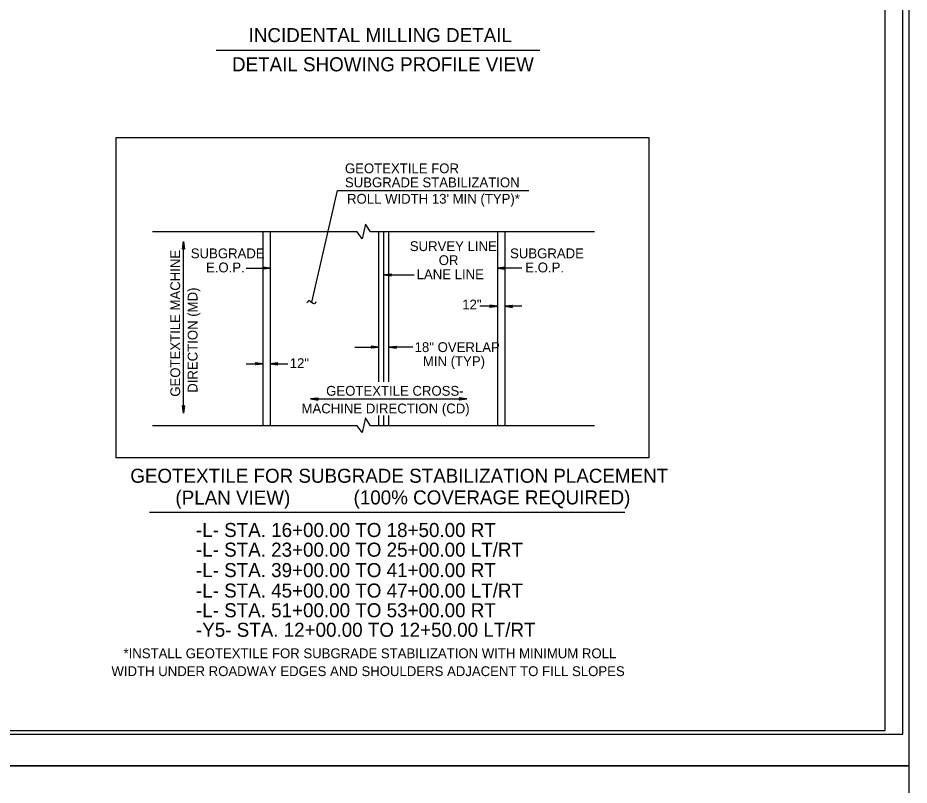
# Model space of a CAD drawing. Extents: x 1901670 to 1902225, y 193498 to 194278.
# Drawn here: x 1902070.8 to 1902134.2, y 194156.6 to 194211.3 of the extents above; entities that cross this region are included whole.
import ezdxf

# ---------------------------------------------------------------- set-up
doc = ezdxf.new("R2010")
doc.units = 0
for name, color, linetype in [('Old_Level_11', 7, 'Continuous'), ('Old_Level_19', 7, 'Continuous'), ('Prop Dimension Text', 7, 'Continuous'), ('Prop Lane Arrow CELL', 7, 'Continuous'), ('Sheet Border Standard 30in CELL', 7, 'Continuous'), ('Sheet Cutting Line CELL', 7, 'Continuous'), ('Sheet Plot Border Inside CELL', 7, 'Continuous'), ('Sheet Plot Border Outside CELL', 7, 'Continuous')]:
    doc.layers.add(name, color=color, linetype=linetype)

msp = doc.modelspace()

# ---------------------------------------------------------------- linework, layer by layer
at = {"layer": 'Old_Level_11'}
msp.add_line((1902084.948, 194208.96), (1902107.972, 194208.96), dxfattribs=at)
msp.add_lwpolyline([(1902077.84, 194202.745), (1902115.712, 194202.745), (1902115.712, 194179.922), (1902077.84, 194179.922)], close=True, dxfattribs=at)
at = {"layer": 'Prop Dimension Text'}
for p, q in [((1902091.746, 194191.002), (1902093.578, 194198.963)), ((1902093.578, 194198.963), (1902107.179, 194198.963)), ((1902088.271, 194196.01), (1902088.271, 194182.216)), ((1902088.786, 194196.01), (1902088.786, 194182.216)), ((1902096.516, 194185.342), (1902096.516, 194196.01)), ((1902096.876, 194185.342), (1902096.876, 194196.01)), ((1902097.236, 194185.342), (1902097.236, 194196.01)), ((1902104.966, 194196.01), (1902104.966, 194182.216)), ((1902105.481, 194196.01), (1902105.481, 194182.216)), ((1902082.619, 194195.323), (1902082.545, 194194.778)), ((1902082.556, 194194.787), (1902082.619, 194195.323)), ((1902082.619, 194195.323), (1902082.566, 194194.798)), ((1902082.577, 194194.808), (1902082.619, 194195.323)), ((1902082.619, 194195.323), (1902082.588, 194194.818)), ((1902082.598, 194194.828), (1902082.619, 194195.323)), ((1902082.619, 194195.323), (1902082.608, 194194.838)), ((1902082.619, 194195.323), (1902082.692, 194194.778)), ((1902082.619, 194194.848), (1902082.619, 194195.323)), ((1902082.629, 194194.838), (1902082.619, 194195.323)), ((1902082.619, 194195.323), (1902082.64, 194194.828)), ((1902082.65, 194194.818), (1902082.619, 194195.323)), ((1902082.619, 194195.323), (1902082.661, 194194.808)), ((1902082.672, 194194.798), (1902082.619, 194195.323)), ((1902082.619, 194195.323), (1902082.682, 194194.787)), ((1902082.619, 194183.107), (1902082.619, 194195.323)), ((1902082.545, 194194.778), (1902082.619, 194194.848)), ((1902082.619, 194194.848), (1902082.692, 194194.778)), ((1902087.072, 194193.429), (1902088.786, 194193.429)), ((1902088.786, 194193.429), (1902088.241, 194193.503)), ((1902088.241, 194193.503), (1902088.311, 194193.429)), ((1902088.786, 194193.429), (1902088.241, 194193.356)), ((1902088.311, 194193.429), (1902088.241, 194193.356)), ((1902088.251, 194193.493), (1902088.786, 194193.429)), ((1902088.786, 194193.429), (1902088.251, 194193.367)), ((1902088.786, 194193.429), (1902088.261, 194193.482)), ((1902088.261, 194193.377), (1902088.786, 194193.429)), ((1902088.271, 194193.472), (1902088.786, 194193.429)), ((1902088.786, 194193.429), (1902088.271, 194193.387)), ((1902088.786, 194193.429), (1902088.282, 194193.461)), ((1902088.282, 194193.398), (1902088.786, 194193.429)), ((1902088.291, 194193.451), (1902088.786, 194193.429)), ((1902088.786, 194193.429), (1902088.291, 194193.409)), ((1902088.786, 194193.429), (1902088.301, 194193.44)), ((1902088.301, 194193.419), (1902088.786, 194193.429)), ((1902088.311, 194193.429), (1902088.786, 194193.429)), ((1902096.876, 194192.957), (1902097.421, 194193.03)), ((1902096.876, 194192.957), (1902097.411, 194193.019)), ((1902097.401, 194193.009), (1902096.876, 194192.957)), ((1902096.876, 194192.957), (1902097.391, 194192.999)), ((1902097.381, 194192.988), (1902096.876, 194192.957)), ((1902097.351, 194192.957), (1902097.421, 194193.03)), ((1902104.966, 194193.429), (1902105.511, 194193.503)), ((1902105.501, 194193.493), (1902104.966, 194193.429)), ((1902104.966, 194193.429), (1902105.491, 194193.482)), ((1902105.481, 194193.472), (1902104.966, 194193.429)), ((1902104.966, 194193.429), (1902105.471, 194193.461)), ((1902105.461, 194193.451), (1902104.966, 194193.429)), ((1902104.966, 194193.429), (1902105.451, 194193.44)), ((1902106.68, 194193.429), (1902104.966, 194193.429)), ((1902104.966, 194193.429), (1902105.511, 194193.356)), ((1902105.441, 194193.429), (1902104.966, 194193.429)), ((1902105.451, 194193.419), (1902104.966, 194193.429)), ((1902104.966, 194193.429), (1902105.461, 194193.409)), ((1902105.471, 194193.398), (1902104.966, 194193.429)), ((1902104.966, 194193.429), (1902105.481, 194193.387)), ((1902105.491, 194193.377), (1902104.966, 194193.429)), ((1902104.966, 194193.429), (1902105.501, 194193.367)), ((1902105.511, 194193.503), (1902105.441, 194193.429)), ((1902105.441, 194193.429), (1902105.511, 194193.356)), ((1902096.876, 194192.957), (1902097.371, 194192.977)), ((1902097.361, 194192.967), (1902096.876, 194192.957)), ((1902096.876, 194192.957), (1902097.421, 194192.883)), ((1902097.411, 194192.893), (1902096.876, 194192.957)), ((1902096.876, 194192.957), (1902097.401, 194192.904)), ((1902097.391, 194192.914), (1902096.876, 194192.957)), ((1902096.876, 194192.957), (1902097.381, 194192.925)), ((1902097.371, 194192.935), (1902096.876, 194192.957)), ((1902096.876, 194192.957), (1902097.361, 194192.946)), ((1902097.351, 194192.957), (1902096.876, 194192.957)), ((1902096.876, 194192.957), (1902099.041, 194192.957)), ((1902097.421, 194192.883), (1902097.351, 194192.957)), ((1902091.415, 194190.97), (1902091.44, 194191.022)), ((1902091.651, 194191.07), (1902091.841, 194190.934)), ((1902092.026, 194190.981), (1902092.062, 194191.049)), ((1902104.966, 194190.716), (1902103.701, 194190.716)), ((1902104.966, 194190.716), (1902104.421, 194190.789)), ((1902104.491, 194190.716), (1902104.421, 194190.789)), ((1902104.966, 194190.716), (1902104.421, 194190.642)), ((1902104.421, 194190.642), (1902104.491, 194190.716)), ((1902104.966, 194190.716), (1902104.431, 194190.778)), ((1902104.431, 194190.652), (1902104.966, 194190.716)), ((1902104.441, 194190.768), (1902104.966, 194190.716)), ((1902104.966, 194190.716), (1902104.441, 194190.663)), ((1902104.966, 194190.716), (1902104.451, 194190.758)), ((1902104.451, 194190.673), (1902104.966, 194190.716)), ((1902104.462, 194190.747), (1902104.966, 194190.716)), ((1902104.966, 194190.716), (1902104.462, 194190.684)), ((1902104.966, 194190.716), (1902104.471, 194190.736)), ((1902104.471, 194190.694), (1902104.966, 194190.716)), ((1902104.481, 194190.726), (1902104.966, 194190.716)), ((1902104.966, 194190.716), (1902104.481, 194190.705)), ((1902104.491, 194190.716), (1902104.966, 194190.716)), ((1902105.481, 194190.716), (1902106.026, 194190.79)), ((1902106.016, 194190.779), (1902105.481, 194190.716)), ((1902105.481, 194190.716), (1902106.006, 194190.768)), ((1902105.996, 194190.758), (1902105.481, 194190.716)), ((1902105.481, 194190.716), (1902105.985, 194190.747)), ((1902105.976, 194190.737), (1902105.481, 194190.716)), ((1902105.481, 194190.716), (1902105.966, 194190.726)), ((1902106.68, 194190.716), (1902105.481, 194190.716)), ((1902105.481, 194190.716), (1902106.026, 194190.642)), ((1902105.956, 194190.716), (1902105.481, 194190.716)), ((1902105.966, 194190.705), (1902105.481, 194190.716)), ((1902105.481, 194190.716), (1902105.976, 194190.695)), ((1902105.985, 194190.684), (1902105.481, 194190.716)), ((1902105.481, 194190.716), (1902105.996, 194190.673)), ((1902106.006, 194190.663), (1902105.481, 194190.716)), ((1902105.481, 194190.716), (1902106.016, 194190.653)), ((1902106.026, 194190.79), (1902105.956, 194190.716)), ((1902105.956, 194190.716), (1902106.026, 194190.642)), ((1902094.815, 194187.814), (1902096.516, 194187.814)), ((1902096.516, 194187.814), (1902095.971, 194187.888)), ((1902095.971, 194187.888), (1902096.041, 194187.814)), ((1902096.516, 194187.814), (1902095.971, 194187.741)), ((1902096.041, 194187.814), (1902095.971, 194187.741)), ((1902095.981, 194187.877), (1902096.516, 194187.814)), ((1902096.516, 194187.814), (1902095.981, 194187.751)), ((1902096.516, 194187.814), (1902095.991, 194187.867)), ((1902095.991, 194187.761), (1902096.516, 194187.814)), ((1902096.001, 194187.856), (1902096.516, 194187.814)), ((1902096.516, 194187.814), (1902096.001, 194187.772)), ((1902096.516, 194187.814), (1902096.012, 194187.845)), ((1902096.012, 194187.783), (1902096.516, 194187.814)), ((1902096.021, 194187.835), (1902096.516, 194187.814)), ((1902096.516, 194187.814), (1902096.021, 194187.793)), ((1902096.516, 194187.814), (1902096.031, 194187.825)), ((1902096.031, 194187.804), (1902096.516, 194187.814)), ((1902096.041, 194187.814), (1902096.516, 194187.814)), ((1902097.236, 194187.814), (1902097.781, 194187.887)), ((1902097.236, 194187.814), (1902097.771, 194187.877)), ((1902097.761, 194187.867), (1902097.236, 194187.814)), ((1902097.236, 194187.814), (1902097.751, 194187.856)), ((1902097.741, 194187.845), (1902097.236, 194187.814)), ((1902097.236, 194187.814), (1902097.731, 194187.835)), ((1902097.721, 194187.824), (1902097.236, 194187.814)), ((1902097.236, 194187.814), (1902097.781, 194187.74)), ((1902097.771, 194187.751), (1902097.236, 194187.814)), ((1902097.236, 194187.814), (1902097.761, 194187.761)), ((1902097.751, 194187.772), (1902097.236, 194187.814)), ((1902097.236, 194187.814), (1902097.741, 194187.783)), ((1902097.731, 194187.793), (1902097.236, 194187.814)), ((1902097.236, 194187.814), (1902097.721, 194187.803)), ((1902097.711, 194187.814), (1902097.236, 194187.814)), ((1902098.937, 194187.814), (1902097.236, 194187.814)), ((1902097.711, 194187.814), (1902097.781, 194187.887)), ((1902097.781, 194187.74), (1902097.711, 194187.814)), ((1902088.271, 194186.631), (1902087.726, 194186.704)), ((1902087.726, 194186.704), (1902087.796, 194186.631)), ((1902087.736, 194186.694), (1902088.271, 194186.631)), ((1902088.271, 194186.631), (1902087.746, 194186.683)), ((1902087.756, 194186.673), (1902088.271, 194186.631)), ((1902088.271, 194186.631), (1902087.767, 194186.662)), ((1902087.776, 194186.652), (1902088.271, 194186.631)), ((1902088.271, 194186.631), (1902087.786, 194186.641)), ((1902088.786, 194186.631), (1902089.331, 194186.704)), ((1902088.786, 194186.631), (1902089.321, 194186.693)), ((1902089.311, 194186.683), (1902088.786, 194186.631)), ((1902088.786, 194186.631), (1902089.301, 194186.673)), ((1902089.29, 194186.662), (1902088.786, 194186.631)), ((1902088.786, 194186.631), (1902089.281, 194186.651)), ((1902089.271, 194186.641), (1902088.786, 194186.631)), ((1902089.261, 194186.631), (1902089.331, 194186.704)), ((1902087.072, 194186.631), (1902088.271, 194186.631)), ((1902088.271, 194186.631), (1902087.726, 194186.557)), ((1902087.796, 194186.631), (1902087.726, 194186.557)), ((1902088.271, 194186.631), (1902087.736, 194186.568)), ((1902087.746, 194186.578), (1902088.271, 194186.631)), ((1902088.271, 194186.631), (1902087.756, 194186.588)), ((1902087.767, 194186.599), (1902088.271, 194186.631)), ((1902088.271, 194186.631), (1902087.776, 194186.61)), ((1902087.786, 194186.62), (1902088.271, 194186.631)), ((1902087.796, 194186.631), (1902088.271, 194186.631)), ((1902088.786, 194186.631), (1902090.051, 194186.631)), ((1902088.786, 194186.631), (1902089.331, 194186.557)), ((1902089.321, 194186.567), (1902088.786, 194186.631)), ((1902088.786, 194186.631), (1902089.311, 194186.578)), ((1902089.301, 194186.588), (1902088.786, 194186.631)), ((1902088.786, 194186.631), (1902089.29, 194186.599)), ((1902089.281, 194186.609), (1902088.786, 194186.631)), ((1902088.786, 194186.631), (1902089.271, 194186.62)), ((1902089.261, 194186.631), (1902088.786, 194186.631)), ((1902089.331, 194186.557), (1902089.261, 194186.631)), ((1902091.652, 194184.121), (1902092.197, 194184.194)), ((1902091.652, 194184.121), (1902092.188, 194184.183)), ((1902092.177, 194184.174), (1902091.652, 194184.121)), ((1902091.652, 194184.121), (1902092.167, 194184.163)), ((1902092.157, 194184.152), (1902091.652, 194184.121)), ((1902091.652, 194184.121), (1902092.147, 194184.141)), ((1902092.137, 194184.131), (1902091.652, 194184.121)), ((1902091.652, 194184.121), (1902092.197, 194184.047)), ((1902092.188, 194184.057), (1902091.652, 194184.121)), ((1902091.652, 194184.121), (1902092.177, 194184.068)), ((1902092.167, 194184.078), (1902091.652, 194184.121)), ((1902091.652, 194184.121), (1902092.157, 194184.09)), ((1902092.147, 194184.099), (1902091.652, 194184.121)), ((1902091.652, 194184.121), (1902092.137, 194184.11)), ((1902092.127, 194184.121), (1902091.652, 194184.121)), ((1902091.652, 194184.121), (1902102.773, 194184.121)), ((1902092.127, 194184.121), (1902092.197, 194184.194)), ((1902092.197, 194184.047), (1902092.127, 194184.121)), ((1902102.773, 194184.12), (1902102.227, 194184.194)), ((1902102.227, 194184.194), (1902102.298, 194184.12)), ((1902102.773, 194184.12), (1902102.227, 194184.047)), ((1902102.298, 194184.12), (1902102.227, 194184.047)), ((1902102.237, 194184.183), (1902102.773, 194184.12)), ((1902102.773, 194184.12), (1902102.237, 194184.057)), ((1902102.773, 194184.12), (1902102.248, 194184.173)), ((1902102.248, 194184.067), (1902102.773, 194184.12)), ((1902102.258, 194184.162), (1902102.773, 194184.12)), ((1902102.773, 194184.12), (1902102.258, 194184.078)), ((1902102.773, 194184.12), (1902102.268, 194184.151)), ((1902102.268, 194184.089), (1902102.773, 194184.12)), ((1902102.277, 194184.141), (1902102.773, 194184.12)), ((1902102.773, 194184.12), (1902102.277, 194184.099)), ((1902102.773, 194184.12), (1902102.288, 194184.131)), ((1902102.288, 194184.11), (1902102.773, 194184.12)), ((1902102.298, 194184.12), (1902102.773, 194184.12)), ((1902082.619, 194183.107), (1902082.546, 194183.652)), ((1902082.619, 194183.582), (1902082.546, 194183.652)), ((1902082.619, 194183.107), (1902082.556, 194183.642)), ((1902082.566, 194183.631), (1902082.619, 194183.107)), ((1902082.619, 194183.107), (1902082.577, 194183.622)), ((1902082.588, 194183.611), (1902082.619, 194183.107)), ((1902082.619, 194183.107), (1902082.598, 194183.602)), ((1902082.609, 194183.591), (1902082.619, 194183.107)), ((1902082.619, 194183.107), (1902082.693, 194183.652)), ((1902082.693, 194183.652), (1902082.619, 194183.582)), ((1902082.683, 194183.642), (1902082.619, 194183.107)), ((1902082.619, 194183.107), (1902082.672, 194183.631)), ((1902082.661, 194183.622), (1902082.619, 194183.107)), ((1902082.619, 194183.107), (1902082.65, 194183.611)), ((1902082.64, 194183.602), (1902082.619, 194183.107)), ((1902082.619, 194183.107), (1902082.63, 194183.591)), ((1902082.619, 194183.582), (1902082.619, 194183.107)), ((1902096.516, 194182.216), (1902096.516, 194182.948)), ((1902096.876, 194182.216), (1902096.876, 194182.948)), ((1902097.236, 194182.216), (1902097.236, 194182.948)), ((1902080.195, 194176.06), (1902114.022, 194176.06))]:
    msp.add_line(p, q, dxfattribs=at)
for points in [[(1902111.856, 194196.01), (1902095.923, 194196.01), (1902095.567, 194196.575), (1902095.34, 194195.521), (1902094.972, 194196.01), (1902080.426, 194196.01)], [(1902111.856, 194182.216), (1902095.923, 194182.216), (1902095.567, 194182.78), (1902095.34, 194181.727), (1902094.972, 194182.216), (1902080.426, 194182.216)]]:
    msp.add_lwpolyline(points, dxfattribs=at)
for centre, radius, start, end in [((1902091.563, 194190.972), 0.132, 48.03212, 157.83099), ((1902091.916, 194191.023), 0.117, 230.47697, 338.76255)]:
    msp.add_arc(centre, radius, start, end, dxfattribs=at)
at = {"layer": 'Sheet Border Standard 30in CELL'}
msp.add_lwpolyline([(1902132.544, 194265.514), (1901982.544, 194265.514), (1901982.544, 194160.514), (1902132.544, 194160.514)], close=True, dxfattribs=at)
at = {"layer": 'Sheet Cutting Line CELL'}
for p, q in [((1902134.244, 194158.014), (1901965.844, 194158.014)), ((1901965.844, 194158.014), (1902134.244, 194158.014))]:
    msp.add_line(p, q, dxfattribs=at)
at = {"layer": 'Sheet Plot Border Inside CELL'}
msp.add_lwpolyline([(1902133.794, 194265.769), (1901967.144, 194265.769), (1901967.144, 194160.259), (1902133.794, 194160.259)], close=True, dxfattribs=at)
at = {"layer": 'Sheet Plot Border Outside CELL'}
for points in [[(1902134.244, 194268.014), (1901965.844, 194268.014), (1901965.844, 194158.014), (1902134.244, 194158.014)], [(1902134.244, 194158.014), (1901965.844, 194158.014), (1901965.844, 194048.014), (1902134.244, 194048.014)]]:
    msp.add_lwpolyline(points, close=True, dxfattribs=at)

# ---------------------------------------------------------------- texts
at = {"layer": 'Old_Level_19'}
for s, p in [('INCIDENTAL MILLING DETAIL', (1902087.254, 194209.523)), ('DETAIL SHOWING PROFILE VIEW', (1902086.068, 194207.444))]:
    msp.add_text(s, height=1, dxfattribs=at).set_placement(p)
at = {"layer": 'Prop Dimension Text'}
for s, p in [('GEOTEXTILE FOR', (1902094.103, 194200.189)), ('SUBGRADE STABILIZATION', (1902094.103, 194199.19)), ("ROLL WIDTH 13' MIN (TYP)*", (1902094.254, 194198.021)), ('SURVEY LINE', (1902098.719, 194194.65)), ('SUBGRADE', (1902083.138, 194194.137)), ('OR', (1902100.777, 194193.651)), ('SUBGRADE', (1902105.851, 194194.137)), ('E.O.P.', (1902084.22, 194193.133)), ('E.O.P.', (1902106.933, 194193.133)), ('LANE LINE', (1902099.206, 194192.645)), ('12"', (1902102.447, 194190.493)), ('18" OVERLAP', (1902099.064, 194187.461)), ('12"', (1902090.178, 194186.318)), ('MIN (TYP)', (1902099.65, 194186.458))]:
    msp.add_text(s, height=0.7, dxfattribs=at).set_placement(p)
for s, height, rotation, p in [('GEOTEXTILE MACHINE', 0.7, 90, (1902082.382, 194184.282)), ('DIRECTION (MD)', 0.7, 90, (1902083.618, 194184.565)), ('GEOTEXTILE CROSS-', 0.7, 360, (1902092.769, 194184.35)), ('MACHINE DIRECTION (CD)', 0.7, 360, (1902091.015, 194183.095)), ('GEOTEXTILE FOR SUBGRADE STABILIZATION PLACEMENT', 0.99999, 360, (1902078.834, 194178.154)), ('(PLAN VIEW)', 0.99999, 360, (1902082.046, 194176.602)), ('(100% COVERAGE REQUIRED)', 0.99999, 360, (1902094.718, 194176.615)), ('*INSTALL GEOTEXTILE FOR SUBGRADE STABILIZATION WITH MINIMUM ROLL', 0.7, 360, (1902078.353, 194165.665)), ('WIDTH UNDER ROADWAY EDGES AND SHOULDERS ADJACENT TO FILL SLOPES', 0.7, 360, (1902077.495, 194164.393))]:
    msp.add_text(s, height=height, rotation=rotation, dxfattribs=at).set_placement(p)
at = {"layer": 'Prop Lane Arrow CELL'}
for s, p in [('-L- STA. 16+00.00 TO 18+50.00 RT', (1902083.507, 194174.294)), ('-L- STA. 23+00.00 TO 25+00.00 LT/RT', (1902083.507, 194172.893)), ('-L- STA. 39+00.00 TO 41+00.00 RT', (1902083.507, 194171.438)), ('-L- STA. 45+00.00 TO 47+00.00 LT/RT', (1902083.507, 194169.983)), ('-L- STA. 51+00.00 TO 53+00.00 RT', (1902083.507, 194168.582)), ('-Y5- STA. 12+00.00 TO 12+50.00 LT/RT', (1902083.507, 194167.191))]:
    msp.add_text(s, height=0.99999, dxfattribs=at).set_placement(p)

doc.saveas('drawing.dxf')
